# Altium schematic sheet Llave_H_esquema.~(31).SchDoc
size A4
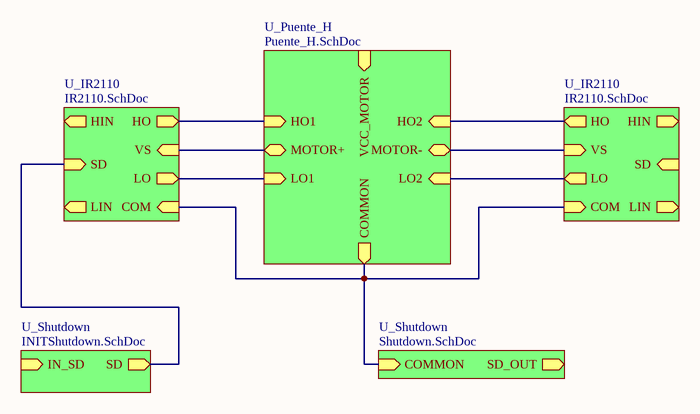
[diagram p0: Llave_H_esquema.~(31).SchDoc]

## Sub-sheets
U_IR2110 = IR2110.SchDoc: SD (in), HIN (out), LIN (out), HO (out), LO (out), VS (in), COM (in)
U_IR2110 = IR2110.SchDoc: SD (in), HIN (out), LIN (out), HO (out), LO (out), VS (in), COM (in)
U_Puente_H = Puente_H.SchDoc: HO1 (in), LO1 (in), HO2 (in), LO2 (in), MOTOR+ (bidir), MOTOR- (bidir), VCC_MOTOR (in), COMMON (out)
U_Shutdown = INITShutdown.SchDoc: IN_SD (in), SD (out)
U_Shutdown = Shutdown.SchDoc: COMMON (in), SD_OUT (out)

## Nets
(unnamed): sheet U_IR2110/SD, sheet U_Shutdown/SD
(unnamed): sheet U_IR2110/HO, sheet U_Puente_H/HO1  [a separate net that carries the same name]
(unnamed): sheet U_IR2110/LO, sheet U_Puente_H/LO1  [a separate net that carries the same name]
(unnamed): sheet U_IR2110/VS, sheet U_Puente_H/MOTOR+  [a separate net that carries the same name]
(unnamed): sheet U_IR2110/COM, sheet U_IR2110/COM, sheet U_Puente_H/COMMON, sheet U_Shutdown/COMMON  [a separate net that carries the same name]
(unnamed): sheet U_IR2110/HO, sheet U_Puente_H/HO2  [a separate net that carries the same name]
(unnamed): sheet U_IR2110/LO, sheet U_Puente_H/LO2  [a separate net that carries the same name]
(unnamed): sheet U_IR2110/VS, sheet U_Puente_H/MOTOR-  [a separate net that carries the same name]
